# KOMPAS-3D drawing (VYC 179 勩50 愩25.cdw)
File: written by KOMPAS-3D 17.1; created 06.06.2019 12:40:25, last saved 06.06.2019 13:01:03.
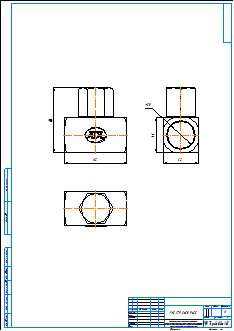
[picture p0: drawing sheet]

Sheet 1: A2, portrait

Title block, sheet 1: name: VYC 179 Ду50 Ру25; material: Внимание! Данный продукт является объектом авторского права ООО «Торговый Дом АДЛ». / Запрещается изменение, копирование, распространение / (в том числе путем копирования на другие сайты и ресурсы в Интернете) / или любое иное использование информации и объектов без предварительного / согласия правообладателя (ООО «Торговый Дом АДЛ»).; sheets: 1; organisation: ООО "Торговый дом АДЛ"; sheet format: A2; stored path: \\adlc.lan\data\АДЛ_ПКД\3D-модели\Поставщики\VYC Industrial\VYC 179\KOMPAS 2D\VYC 179 Ду50 Ру25.cdw

Views: Вид 1, Проекционный вид 2, Проекционный вид 3
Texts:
  user
Dimensions and other numbers on the sheet: 112; 116; 62; 50; 1:1; 1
